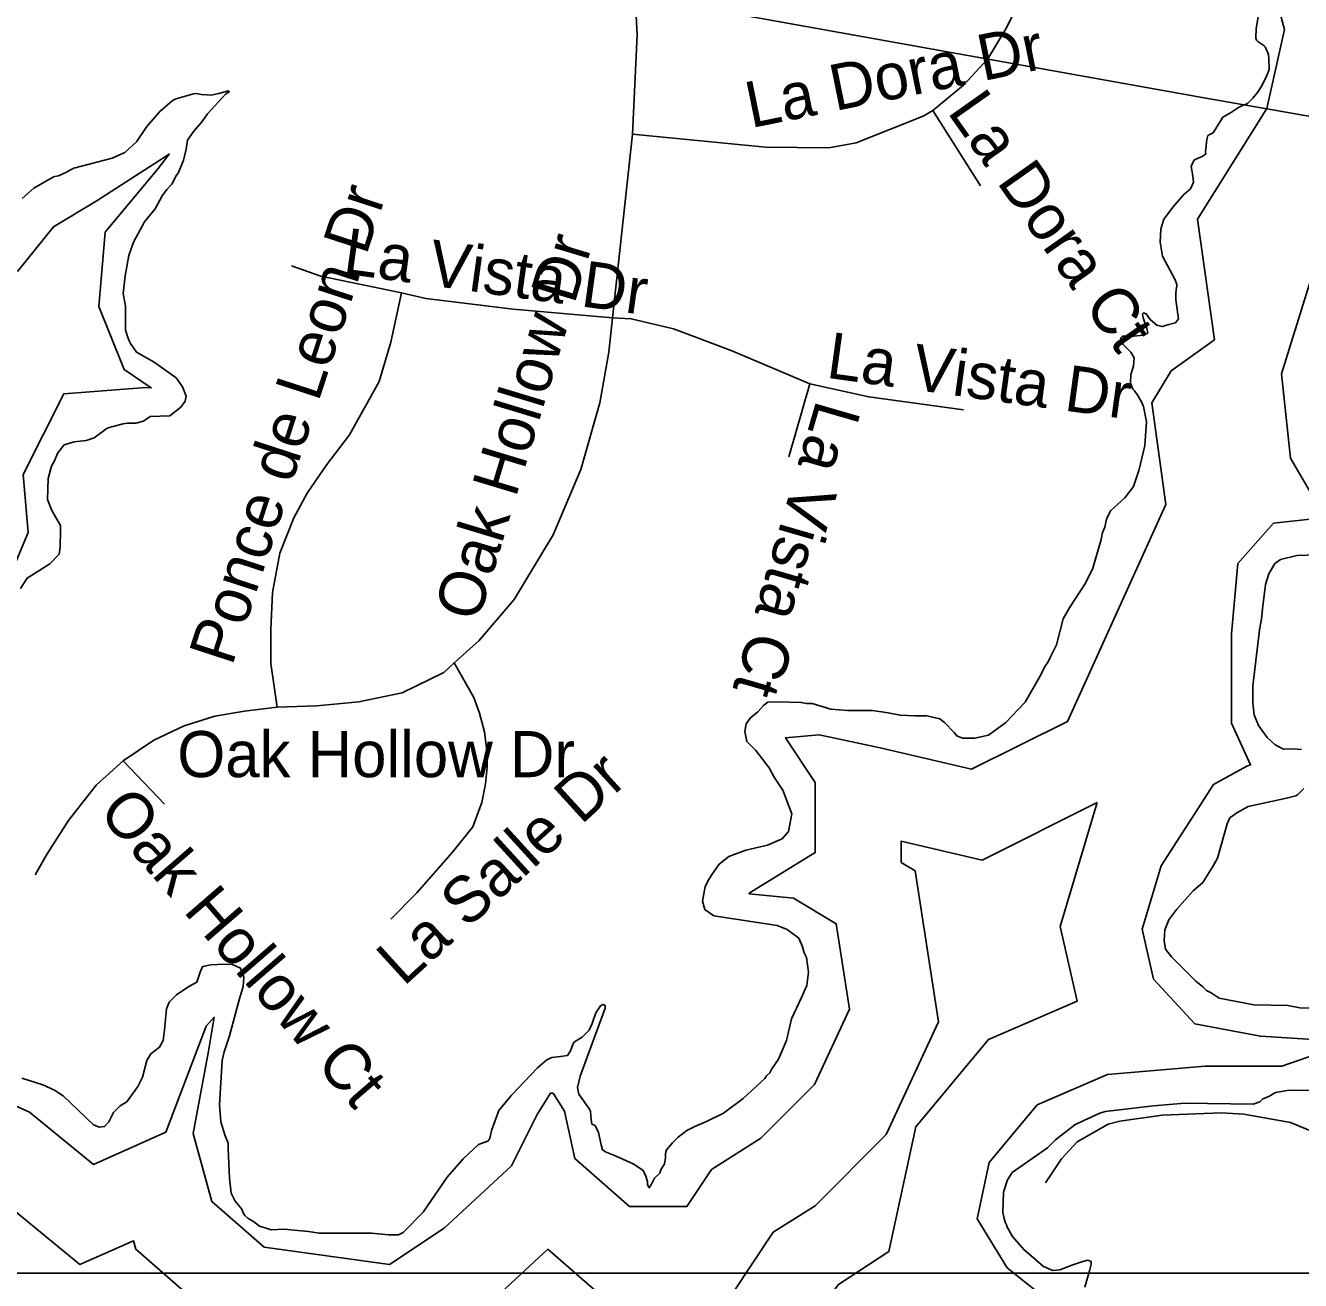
# Model space of a CAD drawing. Extents: x 1662474 to 1856135, y 779280 to 917889.
# Drawn here: x 1707278 to 1709903, y 826573 to 829158 of the extents above; entities that cross this region are included whole.
import ezdxf

# ---------------------------------------------------------------- set-up
doc = ezdxf.new("R2010")
doc.units = 0
for name, color, linetype in [('Exist Hydrographic Lake Shore', 7, 'Continuous'), ('Exist Road Non-System Type 51', 7, 'Continuous'), ('Exist Road Non-System Type 51 Label', 7, 'Continuous'), ('Exist Utilities Electrical Transmission Line', 7, 'Continuous'), ('Map Preparation Inset Cut Line', 7, 'Continuous'), ('Old_Level_44', 7, 'Continuous')]:
    doc.layers.add(name, color=color, linetype=linetype)

msp = doc.modelspace()

# ---------------------------------------------------------------- linework, layer by layer
at = {"layer": 'Exist Hydrographic Lake Shore'}
for points in [[(1709828.1, 829116.5), (1709815.2, 829125.1), (1709812.4, 829128), (1709811.1, 829131.7), (1709812.1, 829151.9), (1709822.6, 829212.6)], [(1709133.9, 827735.9), (1709160.8, 827729.9), (1709170.4, 827722.2), (1709189.9, 827701.8), (1709195.6, 827695), (1709207.6, 827689.8), (1709232.4, 827689.8), (1709260.8, 827695.8), (1709296.9, 827722.2), (1709336.2, 827764.2), (1709366, 827815.4), (1709378.5, 827839.6), (1709382.8, 827845.6), (1709387.5, 827855.9), (1709400.9, 827881.9), (1709414.8, 827935.6), (1709428.1, 827960.1), (1709460.4, 828009.1), (1709475.4, 828040.4), (1709492.8, 828098.9), (1709495.6, 828113.3), (1709500.1, 828124.4), (1709504, 828140.9), (1709511.9, 828158.5), (1709541.5, 828185), (1709559.4, 828208.1), (1709571.2, 828243.2), (1709583, 828293.1), (1709586.4, 828341.9), (1709579.9, 828372.9), (1709575.6, 828382.9), (1709567.2, 828397.6), (1709563.9, 828401.2), (1709561.8, 828405.2), (1709558.1, 828409.1), (1709552.9, 828421.2), (1709553.9, 828438.8), (1709559.6, 828456.4), (1709560.8, 828473.7), (1709553.6, 828485.2), (1709537.4, 828501.5), (1709532.9, 828513.6), (1709537.1, 828518.1), (1709560.4, 828517.8), (1709579.4, 828520.2), (1709588.8, 828524.4), (1709587.2, 828533.6), (1709579.1, 828555.9), (1709577.8, 828564), (1709580.1, 828565.8), (1709585.6, 828563.8), (1709593.8, 828552.2), (1709607.6, 828540.4), (1709618.4, 828537.8), (1709631.9, 828542.4), (1709645.8, 828545.4), (1709652, 828553.8), (1709646.5, 828592.6), (1709646.5, 828605.2), (1709647.2, 828613.9), (1709648.9, 828620.9), (1709648.9, 828624.6), (1709645, 828633.8), (1709618.8, 828683.1), (1709614.5, 828712), (1709615.8, 828738.5), (1709622.1, 828758.8), (1709640.8, 828784.8), (1709662.5, 828809.1), (1709677, 828821.8), (1709682.8, 828835.4), (1709681.1, 828852.7), (1709678.2, 828867.9), (1709682, 828876.9), (1709684.9, 828881.6), (1709692.5, 828885), (1709701.1, 828888.1), (1709708.5, 828893.6), (1709707.6, 828898.1), (1709710.5, 828923.3), (1709712.6, 828931.4), (1709723.6, 828937.2), (1709743.6, 828969.5), (1709759.1, 828977.9), (1709775.6, 828989.4), (1709785.4, 828994.2), (1709791.1, 828996), (1709795.1, 828998.1), (1709805, 829008.6), (1709814.5, 829019.9), (1709822.4, 829031.7), (1709828.1, 829041.9), (1709834.1, 829055.1), (1709838.6, 829067.1), (1709838.1, 829090.5), (1709837.4, 829097.3), (1709836.2, 829101.8), (1709833.6, 829107.8), (1709830.2, 829113.9), (1709828.1, 829116.5)], [(1707271.5, 828801.5), (1707295.6, 828822.8), (1707336.1, 828846.1), (1707338.8, 828847.2), (1707346, 828848.2), (1707362.6, 828856.1), (1707370.8, 828860.8), (1707377.8, 828864), (1707456.8, 828885), (1707482.5, 828896.5), (1707506.4, 828918.6), (1707528.1, 828949.8), (1707554.8, 828981.1), (1707579.9, 829002.6), (1707584.9, 829005.4), (1707590.6, 829007.6), (1707624.2, 829017.2), (1707629, 829018.1), (1707640.2, 829015.7), (1707660.2, 829014.6), (1707676, 829018.1), (1707696.1, 829023.6), (1707697.8, 829021.4), (1707690.9, 829017), (1707652.9, 828976.3), (1707642.1, 828960.3), (1707624.8, 828940.4), (1707611.4, 828922), (1707608.8, 828903.6), (1707603.5, 828880.5), (1707593, 828855.1), (1707588.5, 828848.5), (1707579.1, 828831.2), (1707568.9, 828819.9), (1707559.6, 828807.3), (1707544.8, 828780.5), (1707523.2, 828753.5), (1707500.4, 828711.5), (1707490.9, 828684.4), (1707483, 828642.4), (1707479.1, 828606), (1707484.1, 828580.2), (1707483.9, 828531.4), (1707488.2, 828517.2), (1707491.8, 828508.4), (1707494.6, 828502.8), (1707506.9, 828485), (1707543.1, 828464.8), (1707588, 828432.5), (1707601.1, 828413.6), (1707609, 828394.7), (1707606.6, 828384.4), (1707598, 828371.6), (1707575.4, 828354), (1707535, 828352.7), (1707521.4, 828343.2), (1707505.4, 828339.1), (1707488.2, 828338.6), (1707479.1, 828337.2), (1707461, 828332.8), (1707446, 828328.3), (1707419.2, 828308.6), (1707403.2, 828303.4), (1707378.6, 828300.2), (1707357.4, 828294.4), (1707345, 828277.9), (1707336.9, 828259.6), (1707331.4, 828250.4), (1707324.8, 828224.9), (1707323.2, 828181.6), (1707332.6, 828159.2), (1707350, 828128.3), (1707350.5, 828118.3), (1707349.5, 828083.2), (1707347.6, 828069), (1707328.5, 828049.3), (1707281.5, 828019.6), (1707267.9, 827998.6)], [(1709936.2, 828067.9), (1709895.9, 828066.1), (1709862.2, 828057.7), (1709850.2, 828049.6), (1709837.9, 828028.8), (1709831, 828006.5), (1709824.8, 827956.4), (1709823.1, 827934.9), (1709820, 827921.2), (1709818.8, 827912.1), (1709805.2, 827797.9), (1709805.2, 827762.7), (1709807.9, 827738), (1709817.1, 827716), (1709834.8, 827691.3), (1709850.8, 827676.3), (1709868.2, 827667.1), (1709887.2, 827668.2), (1709905.6, 827666.9)], [(1708351.5, 827027), (1708362, 827032), (1708379.9, 827034.1), (1708394.2, 827036.4), (1708400.1, 827045.6), (1708405.4, 827060.9), (1708408.8, 827064.2), (1708424.2, 827074), (1708438.6, 827088.2), (1708444.8, 827102.3), (1708452.6, 827124.1), (1708461.8, 827138.3), (1708467, 827141.4), (1708471.5, 827139.4), (1708471.5, 827133.6), (1708419.8, 826993.4), (1708414.5, 826970.6), (1708417.4, 826956.7), (1708439.2, 826925.9), (1708441.5, 826920.7), (1708442.9, 826904.4), (1708444.5, 826895), (1708451, 826891.8), (1708457.6, 826877.9), (1708463.1, 826852.2), (1708466, 826841.7), (1708473.9, 826837.2), (1708494, 826828.9), (1708529, 826812.8), (1708549.4, 826800), (1708554.4, 826789.5), (1708558.9, 826776.9), (1708558.9, 826769.8), (1708562.5, 826764), (1708568, 826772.4), (1708573.2, 826783.7), (1708584.1, 826794.2), (1708585.9, 826800.8), (1708594, 826812.8), (1708596.1, 826825.7), (1708595.9, 826834.4), (1708598, 826841.7), (1708610, 826856.7), (1708622.1, 826867.9), (1708639.5, 826882.1), (1708656, 826890), (1708680.1, 826900.5), (1708715.2, 826917.6), (1708755.5, 826947.5), (1708800.4, 826989.2), (1708804, 826994.4), (1708810.4, 827000.8), (1708814.8, 827008.6), (1708828.4, 827028.9), (1708844.8, 827066.9), (1708855.5, 827112.1), (1708875.9, 827155.9), (1708886.8, 827180.3), (1708890.6, 827208.1), (1708886.1, 827238), (1708881.5, 827247.8), (1708877.5, 827262.2), (1708870.4, 827277.7), (1708846.2, 827296.1), (1708826, 827304.2), (1708695.4, 827324.1), (1708676.8, 827336.7), (1708672.2, 827354.3), (1708677.8, 827384.5), (1708685.1, 827398.9), (1708690.4, 827407.6), (1708706.4, 827430.7), (1708726.4, 827445.9), (1708761.5, 827459.3), (1708805.9, 827469.8), (1708835.8, 827482.6), (1708849.4, 827497.6), (1708856, 827533.8), (1708837.1, 827582.9), (1708819.5, 827609.9), (1708809, 827628.6), (1708782, 827664.6), (1708763.4, 827683.4), (1708759.1, 827703.6), (1708762, 827719.6), (1708769.9, 827731.2), (1708785.9, 827744.1), (1708798.2, 827758.2), (1708806.4, 827763.8), (1708828.1, 827765.1), (1708875.4, 827763.5), (1708886.1, 827761.6), (1708897.8, 827761.6), (1708936, 827749.6), (1708970.6, 827746.9), (1709022.1, 827746.7), (1709054.1, 827742.2), (1709078.9, 827737.2), (1709109.2, 827735.9), (1709133.9, 827735.9)], [(1709910, 827586.3), (1709898, 827574), (1709893.8, 827571.1), (1709874.6, 827566.4), (1709795.6, 827549.3), (1709772.2, 827536.4), (1709757.8, 827525.7), (1709752, 827513.4), (1709732.1, 827442.5), (1709722.9, 827425.9), (1709702.1, 827392.9), (1709682.2, 827375.8), (1709648.4, 827337.8), (1709632.1, 827315.8), (1709624, 827294.8), (1709622.9, 827272.9), (1709625.5, 827255.4), (1709637.4, 827239.3), (1709687.5, 827189.5), (1709701.9, 827177.4), (1709709.5, 827170.3), (1709719, 827165.3), (1709735.8, 827154.3), (1709807.4, 827140.4), (1709877.2, 827139.1), (1709901.6, 827134.6), (1709982.8, 827132.2)], [(1707270.8, 826989.5), (1707314, 826975.6), (1707338.1, 826965.1), (1707356, 826953.5), (1707417.8, 826893.4), (1707430, 826888.7), (1707440.8, 826889.8), (1707450, 826899.4), (1707459.6, 826918.9), (1707472.8, 826932.8), (1707486.5, 826940.7), (1707509.2, 826972.1), (1707519.2, 826991.8), (1707528.1, 827025.7), (1707536.4, 827039.6), (1707553.9, 827053.5), (1707561.8, 827067.4), (1707564.6, 827088.2), (1707568.6, 827132.5), (1707574.1, 827146.2), (1707588.9, 827161.4), (1707614.5, 827178.4), (1707630.8, 827187.1), (1707639, 827212.3), (1707642.9, 827219.4), (1707660, 827223.1), (1707673.1, 827223.9), (1707703.2, 827224.1), (1707720.9, 827216), (1707727.9, 827197.6), (1707726.4, 827178.7), (1707718.2, 827151.1), (1707698, 827076.6), (1707687.2, 827043.6), (1707683, 827025.9), (1707677.8, 826934.4), (1707680.6, 826899.7), (1707688.9, 826870.6), (1707695.1, 826855.6), (1707695.1, 826843.8), (1707698, 826783.7), (1707701.9, 826752.5), (1707710.1, 826736.4), (1707723.2, 826719.7), (1707725.5, 826713.6), (1707730, 826706.8), (1707736.6, 826700.8), (1707747.6, 826694.2), (1707760, 826685), (1707784.4, 826677.1), (1707809.8, 826678.4), (1707861, 826673.8), (1707882.8, 826670.3), (1707990.4, 826670.3), (1708025.2, 826666.9), (1708045.8, 826666.9), (1708056, 826671.6), (1708096.6, 826713.4), (1708146.2, 826785.3), (1708179.4, 826823.1), (1708211.1, 826852.8), (1708229.8, 826859.6), (1708234.2, 826865.1), (1708237.9, 826881.6), (1708252.9, 826923.1), (1708278.6, 826954.6), (1708332.6, 827011), (1708351.5, 827027)], [(1709941.5, 826964.3), (1709879.9, 826964.6), (1709851.8, 826959.8), (1709838.4, 826951.7), (1709826, 826946.7), (1709819.5, 826940.9), (1709805.9, 826935.7), (1709665.4, 826938.1), (1709600.6, 826932.8), (1709500.9, 826921), (1709490.4, 826917.3), (1709458.4, 826903.1), (1709438.9, 826893.4), (1709398.5, 826862.2), (1709382.5, 826845.9), (1709309.5, 826795), (1709299.8, 826780.1), (1709291.9, 826754.8)], [(1709291.9, 826754.8), (1709290.1, 826712.6), (1709292.2, 826703.1), (1709295.1, 826692.6), (1709298.5, 826685.8), (1709298.8, 826684), (1709310.6, 826663.5), (1709333.6, 826636.4), (1709374.4, 826601.8), (1709393, 826593.4), (1709407.6, 826595), (1709434.8, 826605.2), (1709454.9, 826612.1), (1709465.6, 826614.4), (1709472.2, 826612.1), (1709472.2, 826606.3), (1709468.6, 826592.4), (1709458.9, 826558.8)]]:
    msp.add_lwpolyline(points, dxfattribs=at)
at = {"layer": 'Exist Road Non-System Type 51'}
for p, q in [((1709244.4, 828827.8), (1709146, 828982.6)), ((1708486.9, 828556.1), (1708527.9, 828934)), ((1708849.9, 828269.2), (1708893.2, 828420.2)), ((1707564.4, 827553.8), (1707478.9, 827643.2))]:
    msp.add_line(p, q, dxfattribs=at)
for points in [[(1709146, 828982.6), (1709209.2, 829035.1), (1709259.4, 829089.2), (1709298.8, 829154.8), (1709333.1, 829225.9), (1709352.9, 829303.6), (1709357, 829377.6), (1709347.6, 829439), (1709328.9, 829486), (1709306.1, 829529), (1709274.9, 829570.5), (1709245.8, 829598.1), (1709190.9, 829632.8), (1709131.6, 829659.2), (1709061.2, 829679.2), (1708989, 829687.6), (1708917.4, 829684.9)], [(1708527.9, 828934), (1708537.4, 829139), (1708528.9, 829308.9), (1708512.1, 829429.9), (1708476.1, 829586)], [(1708527.9, 828934), (1708801.9, 828907.5), (1708931.9, 828906.2), (1708988.2, 828916.2), (1709126.6, 828971.4), (1709146, 828982.6)], [(1707825.9, 828662.9), (1707886.4, 828641.9), (1708052.1, 828607)], [(1707796.4, 827753.5), (1707783.2, 827843.5), (1707783.2, 827913.6), (1707786.4, 827990.2), (1707802.1, 828071.1), (1707830.5, 828143.5), (1707857.9, 828194.4), (1707898.2, 828253.8), (1707945.5, 828314.7), (1708006.4, 828424.9), (1708030, 828505.4), (1708052.1, 828607)], [(1708052.1, 828607), (1708102.6, 828595.8), (1708282.5, 828573.4), (1708486.9, 828556.1)], [(1708160.6, 827845.1), (1708211.6, 827890.2), (1708284.4, 827975.5), (1708364.4, 828108.6), (1708421.6, 828243.2), (1708460.4, 828381), (1708479.1, 828485), (1708486.9, 828556.1)], [(1708486.9, 828556.1), (1708525.2, 828553.5), (1708612.6, 828533.5), (1708731, 828488.7), (1708893.2, 828420.2)], [(1708893.2, 828420.2), (1709014.2, 828392.9), (1709209.2, 828366.4)], [(1707796.4, 827753.5), (1707877.8, 827756.7), (1707964.4, 827764.5), (1708053.9, 827783.2), (1708139.1, 827825.4), (1708160.6, 827845.1)], [(1708030, 827317.2), (1708083.9, 827371.1), (1708157, 827454.9), (1708199, 827507.6), (1708217.6, 827557.4), (1708225.5, 827596), (1708228.6, 827629.9), (1708228.1, 827664), (1708222.9, 827703.1), (1708213.1, 827741.7), (1708201.1, 827773.7), (1708160.6, 827845.1)], [(1707478.9, 827643.2), (1707542.4, 827685.8), (1707604.9, 827715.7), (1707668.1, 827735.1), (1707728.9, 827745.6), (1707796.4, 827753.5)], [(1707297.8, 827408.1), (1707322.6, 827451.7), (1707366.8, 827520.4), (1707423.4, 827592.9), (1707478.9, 827643.2)], [(1710585.4, 826367.7), (1710528.6, 826410.2), (1710058, 826791.4), (1709988, 826845.1), (1709934.1, 826877.1), (1709883, 826898.4), (1709786.4, 826915.7), (1709739.9, 826918.4), (1709618.4, 826913.6), (1709531, 826900.8), (1709507.1, 826895), (1709443.1, 826858.5), (1709410.9, 826823.4), (1709378.5, 826774)]]:
    msp.add_lwpolyline(points, dxfattribs=at)
at = {"layer": 'Exist Utilities Electrical Transmission Line'}
msp.add_lwpolyline([(1704330.5, 829125.1), (1704363.9, 829125.2), (1704441.7, 829122.8), (1704707.5, 829163.8), (1705527.8, 829317.2), (1706167.7, 829434.6), (1706717.3, 829530.9), (1706941.1, 829496.5), (1707139, 829464.5), (1707886.3, 829332.6), (1708789.5, 829173.1), (1709700.6, 829009.5), (1710597.6, 828852.2), (1711504.6, 828682.4), (1712417.9, 828528.9), (1713335, 828365.2)], dxfattribs=at)
at = {"layer": 'Map Preparation Inset Cut Line'}
for points in [[(1731035.7, 826588.1), (1668486.3, 826588.1), (1668486.3, 870408.9), (1731035.7, 870408.9)], [(1731035.7, 782767.4), (1668486.3, 782767.4), (1668486.3, 826588.1), (1731035.7, 826588.1)]]:
    msp.add_lwpolyline(points, close=True, dxfattribs=at)
at = {"layer": 'Old_Level_44'}
for points in [[(1709844.2, 829246.7), (1709870, 829149.9), (1709833.8, 828986.9), (1709691.3, 828759.1)], [(1707242.9, 828016.7), (1707283.5, 828113.9), (1707273.5, 828233), (1707356.8, 828399.3), (1707525.8, 828412.3), (1707537, 828411.3), (1707481.5, 828449.4), (1707429.4, 828579.5), (1707442.2, 828732.2), (1707551.6, 828863.5), (1707574, 828893.3), (1707423.8, 828796.2), (1707335.7, 828743.4), (1707261.9, 828651.2)], [(1709691.3, 828759.1), (1709726.1, 828510.6), (1709636.7, 828446.8), (1709597.3, 828381), (1709625.9, 828171.3), (1709423.7, 827724.6), (1709225.9, 827625.8), (1709038.1, 827669.9), (1708912.3, 827696.9), (1708842.6, 827690.5), (1708904.1, 827598.3), (1708904.1, 827454.3), (1708768.1, 827370.6), (1708767.8, 827369.5), (1708859.6, 827360.4), (1708947.3, 827307.8), (1708974.4, 827131.4), (1708902.9, 826976.4), (1708792.2, 826865.9), (1708690.8, 826801.4), (1708640.1, 826725.4), (1708522, 826725.4), (1708409.4, 826823.8), (1708387.8, 826921.3), (1708364.4, 826958.7), (1708359.3, 826958.7), (1708331.6, 826914.4), (1708279, 826809.2), (1708139.9, 826680.9), (1708027.4, 826606), (1707769.3, 826641.1), (1707661.7, 826735.2), (1707623.4, 826875.8), (1707655.2, 827045.5), (1707666.8, 827115), (1707650.4, 827096.6), (1707567.2, 826878.2), (1707417.8, 826811.8), (1707286.2, 826919.4), (1707107.7, 826999.7)], [(1709949.4, 828152.5), (1709882.7, 828267), (1709864.1, 828440.8), (1709940, 828685.9)], [(1710004.8, 827064.6), (1709820.9, 827075.8), (1709685.4, 827101.6), (1709600.8, 827193.8), (1709577.1, 827296.4), (1709616.3, 827426.7), (1709724.2, 827594.6), (1709792.8, 827632.6), (1709800.4, 827634.8), (1709761.3, 827720.8), (1709761.3, 827904.7), (1709773.9, 828049.6), (1709847.9, 828132.7), (1709967.5, 828146)], [(1709484.9, 827557.2), (1709247.8, 827438.7), (1709081.2, 827477.9), (1709081.2, 827434), (1709109.6, 827416.9), (1709157.6, 827105.6), (1709050.4, 826873.5), (1708903.7, 826726.9), (1708817.4, 826672), (1708734.9, 826548.3), (1708455.5, 826548.3), (1708353.7, 826637.3), (1708249.7, 826541.3), (1708069.8, 826421.5), (1707692.7, 826472.9), (1707505, 826637), (1707500.2, 826654.7), (1707390, 826605.8), (1707192.2, 826767.5)], [(1708747.4, 826058.9), (1708800.3, 826362.8), (1708951.7, 826564.6), (1709055.9, 826632.5), (1709111, 826889.4), (1709260.7, 827068.9), (1709443.6, 827148.4), (1709408.2, 827301.8), (1709484.9, 827557.2)], [(1709387.1, 826529.1), (1709299.5, 826599.1), (1709237.5, 826700), (1709262.3, 826815.8), (1709361.3, 826934.6), (1709505.9, 826997.4), (1709707, 827014.2), (1709864.7, 827014.2), (1709971.9, 827051.4)]]:
    msp.add_lwpolyline(points, dxfattribs=at)

# ---------------------------------------------------------------- texts
at = {"layer": 'Exist Road Non-System Type 51 Label'}
for s, rotation, p in [('La Dora Dr', 11.4794, (1708771.6, 828946.4)), ('La Dora Ct', 305.2026, (1709174.6, 828980.2)), ('Ponce de Leon Dr', 71.9205, (1707703.4, 827836.7)), ('La Vista Dr', 352.1471, (1707929.6, 828647.4)), ('Oak Hollow Dr', 73.1672, (1708209.7, 827926.6)), ('La Vista Dr', 352.1424, (1708924.8, 828432.7)), ('La Vista Ct', 253.8193, (1708907.4, 828389.3)), ('La Salle Dr', 42.3481, (1708056.6, 827177)), ('Oak Hollow Ct', 310.8567, (1707425.5, 827536.3))]:
    msp.add_text(s, height=95, rotation=rotation, dxfattribs=at).set_placement(p)
msp.add_text('Oak Hollow Dr', height=95, dxfattribs=at).set_placement((1707590.6, 827609.6))

doc.saveas('drawing.dxf')
